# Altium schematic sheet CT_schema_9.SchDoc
size 405 x 220 mm
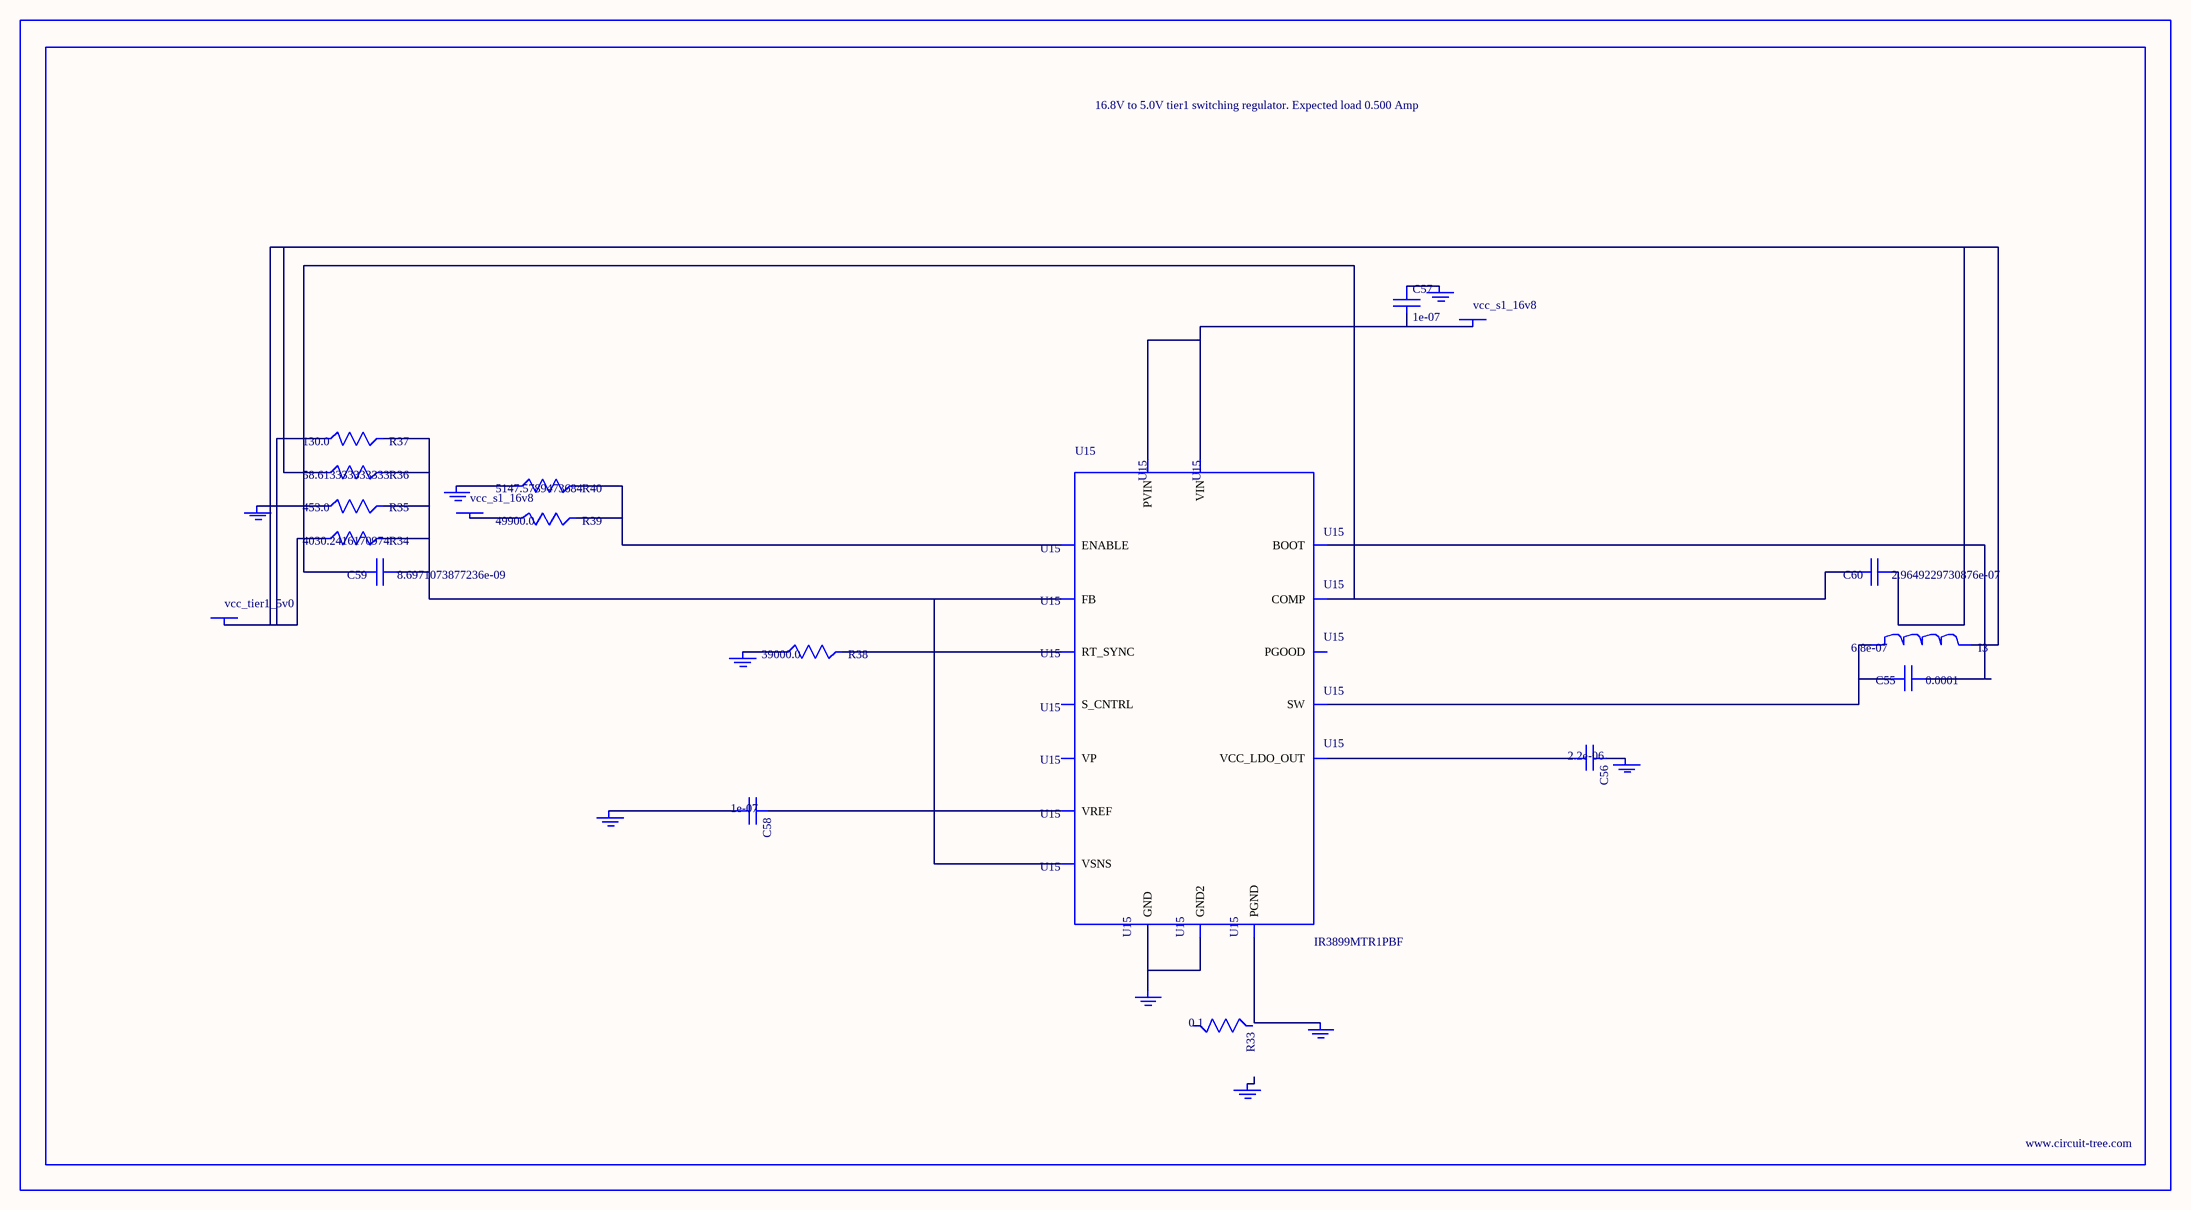
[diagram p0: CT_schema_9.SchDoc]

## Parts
BORDER8  (no value)
C55  0.0001  [C1210]
C56  2.2e-06  [C0603]
C57  1e-07  [C0402]
C58  1e-07  [C0402]
C59  8.6971073877236e-09  [R0603]
C60  2.9649229730876e-07  [R0603]
GND_INSTANCE_8_0  (no value)
GND_INSTANCE_8_1  (no value)
GND_INSTANCE_8_2  (no value)
GND_INSTANCE_8_3  (no value)
GND_INSTANCE_8_4  (no value)
GND_INSTANCE_8_5  (no value)
GND_INSTANCE_8_6  (no value)
GND_INSTANCE_8_7  (no value)
GND_INSTANCE_8_8  (no value)
I3  6.8e-07  [IND25X25CZ]
POWER_INSTANCE_8_0  vcc_s1_16v8
POWER_INSTANCE_8_1  vcc_s1_16v8
POWER_INSTANCE_8_2  vcc_tier1_5v0
R33  0.1  [R0603]
R34  4030.2416170974  [R0603]
R35  453.0  [R0603]
R36  58.613333333333  [R0603]
R37  130.0  [R0603]
R38  39000.0  [R0603]
R39  49900.0  [R0603]
R40  5147.5789473684  [R0603]
U15  IR3899MTR1PBF  [IR3899MTR1PBF]

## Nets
NetC55_1: C55.1 U15.14(BOOT)
NetC55_2: C55.2 I3.1 U15.12(SW)
NetC56_1: C56.1 GND_INSTANCE_8_4.0(GND)
NetC56_2: C56.2 U15.10(VCC_LDO_OUT)
NetC57_1: C57.1 GND_INSTANCE_8_3.0(GND)
NetC57_2: C57.2 POWER_INSTANCE_8_0.0(PWR) U15.9(VIN) U15.13(PVIN)
NetC58_1: C58.1 U15.2(VREF)
NetC58_2: C58.2 GND_INSTANCE_8_1.0(GND)
NetC59_1: C59.1 R34.2 R35.2 R36.2 R37.2 U15.1(FB) U15.8(VSNS)
NetC59_2: C59.2 C60.2 U15.3(COMP)
NetC60_1: C60.1 I3.2 POWER_INSTANCE_8_2.0(PWR) R34.1 R36.1 R37.1
NetGND_INSTANCE_8_0_0: GND_INSTANCE_8_0.0(GND) R35.1
NetGND_INSTANCE_8_2_0: GND_INSTANCE_8_2.0(GND) R38.1
NetGND_INSTANCE_8_6_0: GND_INSTANCE_8_6.0(GND) U15.11(PGND)
NetGND_INSTANCE_8_7_0: GND_INSTANCE_8_7.0(GND) R40.1
NetGND_INSTANCE_8_8_0: GND_INSTANCE_8_8.0(GND) U15.4(GND) U15.17(GND2)
NetPOWER_INSTANCE_8_1_0: POWER_INSTANCE_8_1.0(PWR) R39.1
NetR38_2: R38.2 U15.5(RT_SYNC)
NetR39_2: R39.2 R40.2 U15.15(ENABLE)

Not connected (* = marked no-connect by the designer): GND_INSTANCE_8_5 0(GND); R33 1 2; U15 6(S_CNTRL) 7(PGOOD) 16(VP)

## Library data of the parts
BORDER8 = BORDER_PAGE8
C55 = GRM32ER61A107ME20L
C56 = C0603C225K8RACTU
C57 C58 = C0402C104K3RACTU
C59 = C59
C60 = C60
GND_INSTANCE_8_0-GND_INSTANCE_8_8 = GND
I3 = IHLP2525CZERR68M01
POWER_INSTANCE_8_0-POWER_INSTANCE_8_2 = PWR
R33 = ERJ-3RSFR10V
R34 = R34
R35 = ERJ-3EKF4530V
R36 = R36
R37 = RC0603JR-07130RL
R38 = RC0603JR-0739KL
R39 = RC0603FR-0749K9
R40 = R40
